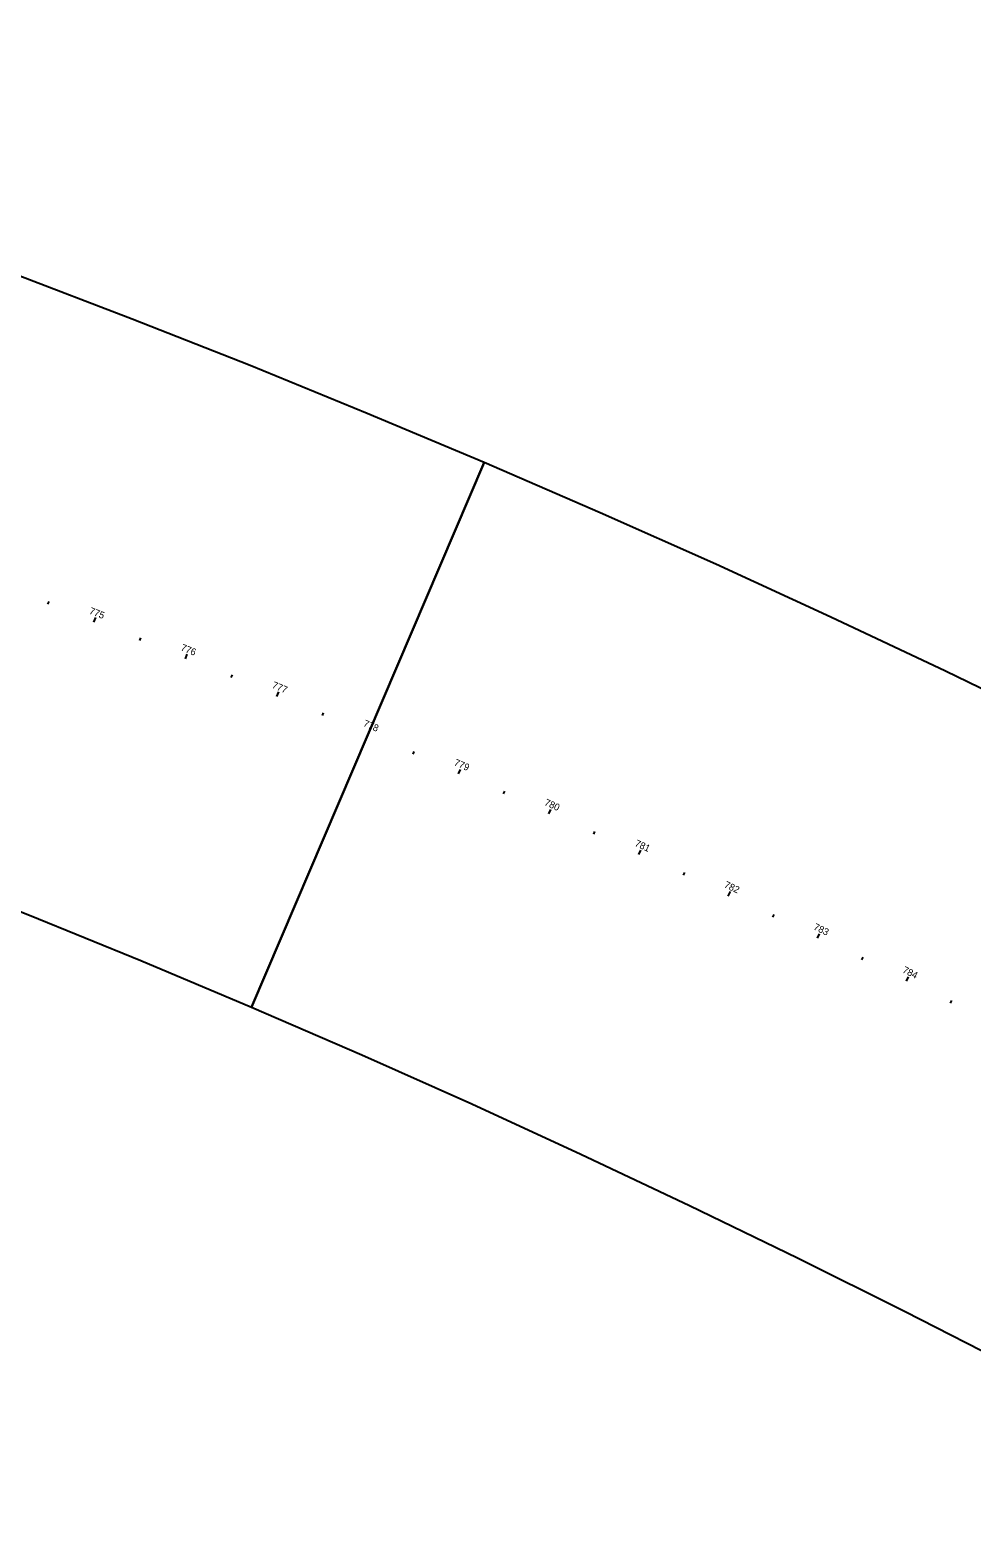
# Model space of a CAD drawing. Extents: x 75725 to 90554, y 518585 to 527848.
# Drawn here: x 80279 to 81233, y 525757 to 527285 of the extents above; entities that cross this region are included whole.
import ezdxf

# ---------------------------------------------------------------- set-up
doc = ezdxf.new("R2010")
doc.units = 0
doc.layers.add('GE_P_Alignment_100_Stations', color=7, linetype='Continuous')
doc.layers.add('SH_Named_Boundary', color=7, linetype='Continuous')

msp = doc.modelspace()

# ---------------------------------------------------------------- linework, layer by layer
at = {"layer": 'GE_P_Alignment_100_Stations'}
for p, q in [((80296.8, 526703), (80297.9, 526705.8)), ((80343.3, 526684.7), (80345.2, 526689.4)), ((80389.8, 526666.2), (80390.9, 526669)), ((80436.2, 526647.5), (80438, 526652.2)), ((80482.4, 526628.6), (80483.6, 526631.4)), ((80528.6, 526609.5), (80530.6, 526614.1)), ((80574.8, 526590.2), (80575.9, 526592.9)), ((80620.8, 526570.7), (80622.8, 526575.2)), ((80666.7, 526550.9), (80667.9, 526553.7)), ((80712.6, 526531), (80714.6, 526535.6)), ((80758.4, 526510.9), (80759.6, 526513.6)), ((80804.1, 526490.6), (80806.1, 526495.1)), ((80849.7, 526470.1), (80850.9, 526472.8)), ((80895.2, 526449.3), (80897.2, 526453.9)), ((80940.6, 526428.4), (80941.8, 526431.1)), ((80985.9, 526407.3), (80988, 526411.8)), ((81031.1, 526386), (81032.4, 526388.7)), ((81076.3, 526364.5), (81078.4, 526369)), ((81121.3, 526342.8), (81122.6, 526345.5)), ((81166.3, 526320.9), (81168.5, 526325.4)), ((81211.1, 526298.8), (81212.4, 526301.5))]:
    msp.add_line(p, q, dxfattribs=at)
at = {"layer": 'SH_Named_Boundary'}
for points in [[(79533.6, 527284.6), (79359.6, 526710.4), (79475.9, 526674.5), (79591.8, 526637.3), (79707.3, 526598.8), (79822.4, 526559.1), (79937, 526518.1), (80051.2, 526475.9), (80164.9, 526432.5), (80278.1, 526387.8), (80390.9, 526341.9), (80503.1, 526294.7), (80738.5, 526846.6), (80620.3, 526896.3), (80501.5, 526944.7), (80382.2, 526991.8), (80262.3, 527037.6), (80142, 527082), (80021.2, 527125.2), (79900, 527167.1), (79778.3, 527207.6), (79656.1, 527246.8)], [(80738.5, 526846.6), (80503.1, 526294.7), (80614.8, 526246.3), (80726, 526196.7), (80836.6, 526145.9), (80946.6, 526093.9), (81056.1, 526040.7), (81165, 525986.3), (81273.3, 525930.8), (81381, 525874), (81488.1, 525816.1), (81594.5, 525757), (81888.6, 526280), (81776.5, 526342.2), (81663.7, 526403.3), (81550.2, 526463.1), (81436.1, 526521.6), (81321.3, 526579), (81205.9, 526635), (81089.9, 526689.8), (80973.4, 526743.4), (80856.2, 526795.6)]]:
    msp.add_lwpolyline(points, close=True, dxfattribs=at)

# ---------------------------------------------------------------- texts
at = {"layer": 'GE_P_Alignment_100_Stations'}
for s, rotation, p in [('775', 338.3972, (80338, 526693.6)), ('776', 337.8972, (80430.7, 526656.5)), ('777', 337.3972, (80523.2, 526618.5)), ('778', 336.8972, (80615.6, 526579.7)), ('779', 336.3972, (80707.5, 526540.1)), ('780', 335.8972, (80799, 526499.7)), ('781', 335.3972, (80890.6, 526458.3)), ('782', 334.8972, (80981.1, 526416.4)), ('783', 334.3972, (81071.6, 526373.7)), ('784', 333.8972, (81161.7, 526330.1))]:
    msp.add_text(s, height=7, rotation=rotation, dxfattribs=at).set_placement(p)

doc.saveas('drawing.dxf')
